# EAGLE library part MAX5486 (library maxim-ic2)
MAX5486 TSSOP24
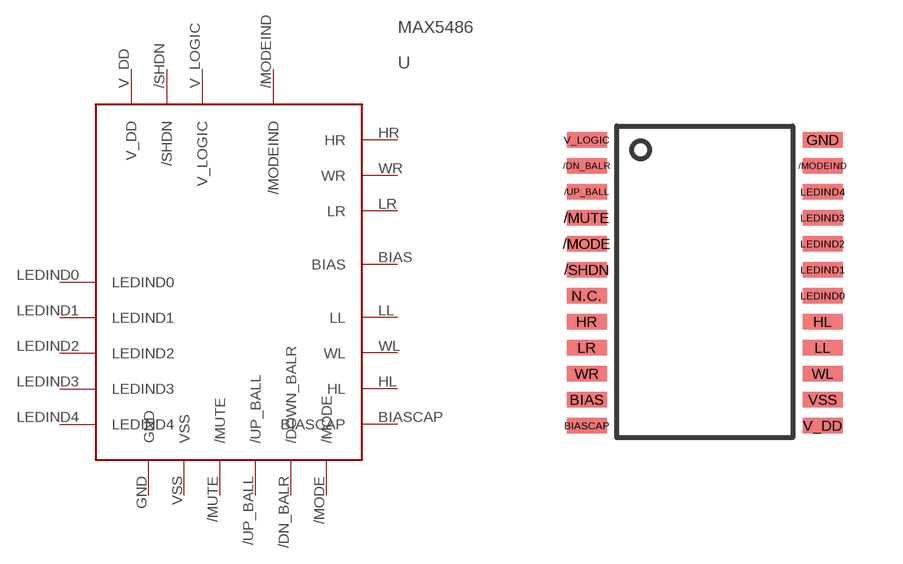
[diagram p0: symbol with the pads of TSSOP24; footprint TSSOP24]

Designator prefix -

## MAX5486  [TSSOP24]
/DN_BALR  /DOWN_BALR  in
/MODE  /MODE  in
/MODEIND  /MODEIND  in
/MUTE  /MUTE  in
/SHDN  /SHDN  in
/UP_BALL  /UP_BALL  in
BIAS  BIAS  out
BIASCAP  BIASCAP
GND  GND  pwr
HL  HL  in
HR  HR  in
LEDIND0  LEDIND0  in
LEDIND1  LEDIND1  in
LEDIND2  LEDIND2  in
LEDIND3  LEDIND3  in
LEDIND4  LEDIND4  in
LL  LL
LR  LR
V_DD  V_DD  pwr
V_LOGIC  V_LOGIC  pwr
VSS  VSS  pwr
WL  WL  out
WR  WR  out

## Footprint TSSOP24 (pad centres in mm)
smd 1 x 0.38: /DN_BALR -0.75,6.8; /MODE -0.75,4.85; /MODEIND 5.15,6.8; /MUTE -0.75,5.5; /SHDN -0.75,4.2; /UP_BALL -0.75,6.15; BIAS -0.75,0.95; BIASCAP -0.75,0.3; GND 5.15,7.45; HL 5.15,2.9; HR -0.75,2.9; LEDIND0 5.15,3.55; LEDIND1 5.15,4.2; LEDIND2 5.15,4.85; LEDIND3 5.15,5.5; LEDIND4 5.15,6.15; LL 5.15,2.25; LR -0.75,2.25; N.C. -0.75,3.55; V_DD 5.15,0.3; V_LOGIC -0.75,7.45; VSS 5.15,0.95; WL 5.15,1.6; WR -0.75,1.6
